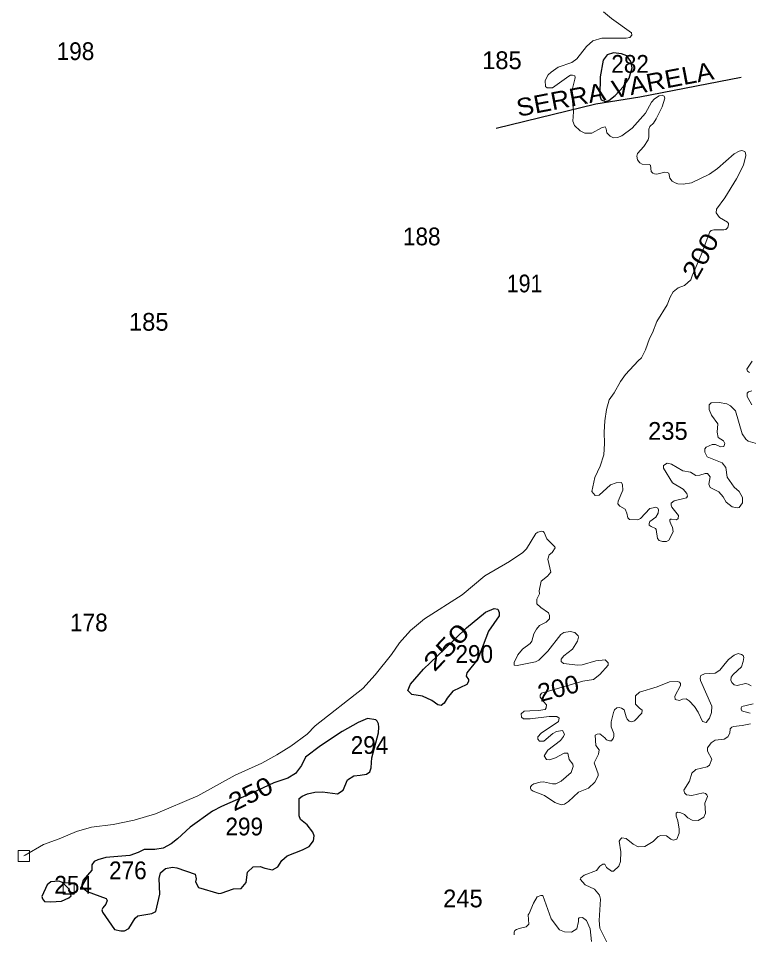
# Model space of a CAD drawing. Extents: x 499.9 to 555.3, y 9281.5 to 9336.8.
# Drawn here: x 499.95 to 506.54, y 9288.5 to 9296.75 of the extents above; entities that cross this region are included whole.
import ezdxf
from ezdxf.enums import TextEntityAlignment as Align

# ---------------------------------------------------------------- set-up
doc = ezdxf.new("R2010")
doc.units = 0
doc.header["$LTSCALE"] = 0.064
for name, color, linetype, lineweight in [('1', 7, 'Continuous', 25), ('2', 7, 'Continuous', 13), ('26', 7, 'Continuous', 25), ('62', 7, 'Continuous', 13)]:
    doc.layers.add(name, color=color, linetype=linetype, lineweight=lineweight)
doc.layers.add('21', color=7, linetype='Continuous')
doc.layers.add('61', color=7, linetype='Continuous')

msp = doc.modelspace()

# ---------------------------------------------------------------- linework, layer by layer
at = {"layer": '1'}
for points in [[(505.3309, 9296.058), (505.407, 9296.1414), (505.4595, 9296.2165), (505.485, 9296.3096), (505.4745, 9296.3666), (505.4378, 9296.4165), (505.3896, 9296.436), (505.3169, 9296.4447), (505.2599, 9296.4266), (505.2231, 9296.3782), (505.1979, 9296.2277), (505.1944, 9296.0552), (505.207, 9296.0211), (505.2446, 9296.0061), (505.2762, 9296.0136)], [(503.6048, 9290.8873), (503.793, 9291.0695), (503.9922, 9291.2624), (504.1617, 9291.4023), (504.2416, 9291.4356), (504.2728, 9291.4305), (504.2868, 9291.3979), (504.2847, 9291.3702), (504.1912, 9291.23), (504.0936, 9290.978), (503.9949, 9290.8566), (503.9871, 9290.8241), (504.0098, 9290.795), (504.011, 9290.7771), (503.9932, 9290.7503), (503.867, 9290.6911), (503.8173, 9290.6278), (503.7889, 9290.5817), (503.762, 9290.5613), (503.7325, 9290.5664), (503.6782, 9290.6057), (503.5938, 9290.6463), (503.4983, 9290.661), (503.4615, 9290.6964), (503.4856, 9290.7541)], [(503.1208, 9289.9623), (503.1331, 9289.9996), (503.1346, 9290.048), (503.1381, 9290.088), (503.1989, 9290.3153), (503.2024, 9290.3649), (503.1968, 9290.3964), (503.185, 9290.4208), (503.1741, 9290.4331), (503.0991, 9290.4427), (503.0157, 9290.4061), (502.8707, 9290.3254), (502.6737, 9290.1977), (502.5397, 9290.0959), (502.5023, 9290.0206), (502.4493, 9289.9487), (502.3795, 9289.9064), (502.2536, 9289.8648), (502.0553, 9289.771), (501.7833, 9289.6508), (501.6999, 9289.6078), (501.4986, 9289.4656), (501.3849, 9289.3602), (501.3274, 9289.3152), (501.2577, 9289.2756), (501.1802, 9289.2622), (501.0838, 9289.262), (501.0306, 9289.2351), (500.9566, 9289.2095), (500.7379, 9289.1919), (500.6668, 9289.1704), (500.6354, 9289.1537), (500.6142, 9289.1242), (500.613, 9289.0769), (500.5357, 9288.9851), (500.5227, 9288.9438), (500.5298, 9288.9191), (500.5699, 9288.885), (500.7434, 9288.8224), (500.7505, 9288.804), (500.7379, 9288.7704), (500.7113, 9288.7382), (500.7043, 9288.72), (500.7098, 9288.6965), (500.8164, 9288.5409), (500.8736, 9288.5283), (500.9063, 9288.529), (500.9478, 9288.5508), (501.0037, 9288.6445), (501.0271, 9288.6647), (501.154, 9288.6859), (501.1895, 9288.7037), (501.2247, 9288.8611), (501.219, 9289.0022), (501.2323, 9289.054), (501.2768, 9289.0906), (501.3418, 9289.104), (501.3797, 9289.0974), (501.5454, 9289.0394), (501.5525, 9288.998), (501.5485, 9288.9701), (501.5756, 9288.9217), (501.7589, 9288.8673), (501.7787, 9288.8681), (501.8893, 9288.9084), (501.9592, 9288.9121), (502.0043, 9288.9662), (502.0178, 9289.0597), (502.0678, 9289.1054), (502.132, 9289.1092), (502.1735, 9289.0934), (502.242, 9289.08), (502.2909, 9289.1064), (502.3253, 9289.1639), (502.3741, 9289.2062), (502.5116, 9289.2593), (502.5725, 9289.2898), (502.6129, 9289.34), (502.6173, 9289.387), (502.6057, 9289.4203), (502.5536, 9289.4849), (502.4956, 9289.5338), (502.4812, 9289.5676), (502.4836, 9289.7214), (502.5109, 9289.7426), (502.5568, 9289.7642), (502.6246, 9289.7807), (502.6922, 9289.7825), (502.8298, 9289.7657), (502.8782, 9289.7971), (502.9188, 9289.8915), (502.9764, 9289.9273), (503.0337, 9289.9325), (503.0889, 9289.9422)]]:
    msp.add_lwpolyline(points, close=True, dxfattribs=at)
msp.add_lwpolyline([(500.4036, 9288.9116), (500.3499, 9288.9664), (500.3139, 9288.9788), (500.2434, 9288.9701), (500.2098, 9288.943), (500.1632, 9288.8379), (500.1678, 9288.8193), (500.186, 9288.7956), (500.2441, 9288.7898), (500.3379, 9288.7985), (500.4041, 9288.827), (500.4255, 9288.8447), (500.405, 9288.9131)], dxfattribs=at)
at = {"layer": '2'}
for points in [[(505.2266, 9296.8135), (505.2993, 9296.752), (505.4793, 9296.6254), (505.4831, 9296.602), (505.4639, 9296.5832), (505.4305, 9296.5771), (505.2133, 9296.5752), (505.1306, 9296.5513), (505.0747, 9296.5005), (504.9872, 9296.3896), (504.9411, 9296.3575), (504.8186, 9296.3159), (504.7543, 9296.2708), (504.7286, 9296.2448), (504.7017, 9296.1951), (504.7046, 9296.1405), (504.7194, 9296.1287), (504.7682, 9296.1271), (504.9135, 9296.2342), (504.9309, 9296.2422), (504.948, 9296.244), (504.9676, 9296.2375), (504.9715, 9296.2219), (504.9696, 9296.2063), (504.9464, 9296.1219), (504.9412, 9296.0787), (504.9553, 9295.9132), (504.9491, 9295.8292), (504.9663, 9295.7883), (505.017, 9295.7403), (505.0592, 9295.7191), (505.1209, 9295.7208), (505.2094, 9295.768), (505.2417, 9295.7757), (505.2517, 9295.7603), (505.2585, 9295.7218), (505.2881, 9295.6921), (505.3175, 9295.6779), (505.3533, 9295.6795), (505.3931, 9295.6953), (505.4854, 9295.7637), (505.6062, 9295.9005), (505.659, 9296), (505.6875, 9296.0299), (505.7296, 9296.0567), (505.7552, 9296.0633), (505.774, 9296.0539), (505.781, 9296.0363), (505.7574, 9295.9577), (505.7024, 9295.8482), (505.6766, 9295.8102), (505.6448, 9295.7799), (505.6366, 9295.7573), (505.6354, 9295.6861), (505.63, 9295.6602), (505.5919, 9295.5982), (505.5348, 9295.5368), (505.5286, 9295.5112), (505.5329, 9295.4788), (505.5534, 9295.4523), (505.5748, 9295.4413), (505.6395, 9295.4385), (505.6509, 9295.4314), (505.6561, 9295.3757), (505.6722, 9295.3597), (505.6869, 9295.3546), (505.7075, 9295.3511), (505.7809, 9295.3676), (505.801, 9295.3666), (505.8162, 9295.3593), (505.825, 9295.3136), (505.8461, 9295.2872), (505.8735, 9295.2709), (505.8985, 9295.2639), (505.9445, 9295.2595), (506.0218, 9295.2719)], [(506.4746, 9295.5625), (506.5012, 9295.5531), (506.5088, 9295.5393), (506.51, 9295.5199), (506.4894, 9295.4319), (506.4264, 9295.3091), (506.3214, 9295.1372), (506.2446, 9295.0355), (506.2426, 9295.0016), (506.2737, 9294.9595), (506.3441, 9294.9171), (506.3542, 9294.906), (506.3552, 9294.8963), (506.3476, 9294.8695), (506.3306, 9294.8527), (506.3126, 9294.8477), (506.2219, 9294.8487), (506.1978, 9294.8422), (506.1853, 9294.8311), (506.108, 9294.623), (506.0273, 9294.4333), (506.0141, 9294.3964), (505.9569, 9294.3477), (505.9009, 9294.3247), (505.8552, 9294.2881), (505.8277, 9294.2421), (505.801, 9294.1735), (505.7067, 9294.0224), (505.6703, 9293.9214), (505.6407, 9293.8679), (505.606, 9293.7671), (505.57, 9293.6937), (505.5387, 9293.6682), (505.426, 9293.5442), (505.3789, 9293.4813), (505.3247, 9293.3796), (505.2769, 9293.3166), (505.2548, 9293.2275), (505.2388, 9293.1256), (505.2324, 9293.0237), (505.2371, 9292.9211), (505.229, 9292.8192), (505.1976, 9292.7182), (505.1481, 9292.6155), (505.1212, 9292.489), (505.1514, 9292.4551), (505.1893, 9292.4582), (505.2897, 9292.5486), (505.3406, 9292.5692), (505.3879, 9292.5704), (505.398, 9292.5487), (505.4006, 9292.5018), (505.3586, 9292.4029), (505.3577, 9292.3772), (505.3734, 9292.3578), (505.4225, 9292.3307), (505.4386, 9292.2946), (505.447, 9292.2533), (505.4625, 9292.237), (505.5354, 9292.234), (505.5601, 9292.2465), (505.6456, 9292.3379), (505.6748, 9292.3431), (505.6998, 9292.3475), (505.716, 9292.3391), (505.7231, 9292.3242), (505.7189, 9292.2941), (505.6986, 9292.2584), (505.6457, 9292.2197), (505.6398, 9292.2002), (505.6396, 9292.1862), (505.6574, 9292.1732), (505.696, 9292.1565), (505.7034, 9292.1462), (505.7153, 9292.0675), (505.7291, 9292.0496), (505.7587, 9292.0387), (505.7963, 9292.0383), (505.8157, 9292.0518), (505.8558, 9292.1254), (505.8501, 9292.1681), (505.8373, 9292.1906), (505.8254, 9292.2209), (505.8254, 9292.2341), (505.8301, 9292.2416), (505.8404, 9292.2416), (505.8856, 9292.2352), (505.9011, 9292.2459), (505.9031, 9292.2743), (505.8434, 9292.3472), (505.8374, 9292.3672), (505.8387, 9292.3847), (505.8637, 9292.4042), (505.9744, 9292.4333), (505.9833, 9292.4475)], [(506.0218, 9295.2719), (506.1818, 9295.3511), (506.2539, 9295.4003), (506.4054, 9295.5327), (506.4501, 9295.5581), (506.4746, 9295.5625)], [(506.5439, 9293.5627), (506.5242, 9293.5735), (506.5193, 9293.5925), (506.5686, 9293.6653)], [(506.564, 9293.2719), (506.5215, 9293.345), (506.5234, 9293.3761), (506.536, 9293.3873), (506.5638, 9293.3969)], [(505.7676, 9292.7236), (505.8013, 9292.7457), (505.8403, 9292.7363), (505.9416, 9292.6766), (506.0122, 9292.6646), (506.0593, 9292.6349), (506.0958, 9292.6381), (506.1451, 9292.6534), (506.1649, 9292.6517), (506.19, 9292.6214), (506.178, 9292.5558), (506.1877, 9292.5266), (506.2674, 9292.4859), (506.3076, 9292.4426), (506.333, 9292.3942), (506.3863, 9292.351), (506.4324, 9292.3419), (506.4514, 9292.3453), (506.4798, 9292.3865), (506.4798, 9292.4371), (506.4495, 9292.4887), (506.4054, 9292.5296), (506.3411, 9292.6204), (506.3299, 9292.7052), (506.2962, 9292.7478), (506.1632, 9292.8027), (506.1398, 9292.8448), (506.1397, 9292.8741), (506.152, 9292.8902), (506.2077, 9292.9139), (506.2357, 9292.9143), (506.2833, 9292.8911), (506.3127, 9292.8965), (506.3222, 9292.9227), (506.3103, 9292.9466), (506.2605, 9292.9777), (506.2511, 9293.0261), (506.2568, 9293.1), (506.2022, 9293.1783), (506.1796, 9293.2299), (506.1811, 9293.2702), (506.1993, 9293.2891), (506.2692, 9293.2935), (506.3407, 9293.2803), (506.3719, 9293.2616), (506.418, 9293.2164), (506.4768, 9293.011), (506.512, 9292.961), (506.5303, 9292.9448), (506.6589, 9292.9061)], [(505.9833, 9292.4475), (505.9797, 9292.4728), (505.9442, 9292.5118), (505.8505, 9292.568), (505.7677, 9292.7009), (505.7676, 9292.7236)], [(504.5671, 9291.1183), (504.5798, 9291.141), (504.599, 9291.2054), (504.6226, 9291.2484), (504.6495, 9291.2812), (504.7103, 9291.3106), (504.7386, 9291.3424), (504.7394, 9291.3712), (504.7319, 9291.3967), (504.6612, 9291.4437), (504.6271, 9291.4773), (504.6247, 9291.5204), (504.6496, 9291.5667), (504.6471, 9291.5938), (504.666, 9291.6812), (504.7235, 9291.7281), (504.7529, 9291.7614), (504.7249, 9291.8793), (504.7376, 9291.9183), (504.7632, 9291.9414), (504.7899, 9291.9833), (504.7893, 9291.9922), (504.7165, 9292.0624), (504.6928, 9292.1198), (504.6826, 9292.1279), (504.6669, 9292.1311), (504.6348, 9292.1237), (504.6182, 9292.1125), (504.5324, 9291.9733), (504.4986, 9291.9407), (504.3803, 9291.8591), (504.1558, 9291.7286), (503.9529, 9291.5586), (503.6138, 9291.3407), (503.4859, 9291.2367), (503.3874, 9291.1258), (503.3166, 9291.0215), (503.1678, 9290.8377), (503.0568, 9290.7135), (502.6281, 9290.3785), (502.5543, 9290.3018), (502.4067, 9290.1943), (502.2809, 9290.1147), (502.1447, 9290.0419), (501.9068, 9289.9325), (501.5679, 9289.7456), (501.1874, 9289.5854), (500.9942, 9289.5284), (500.8049, 9289.4888), (500.6113, 9289.4644), (500.4743, 9289.4264), (500.3169, 9289.359), (500.1762, 9289.309), (500.0105, 9289.2112), (500, 9289.205)], [(505.2397, 9290.2701), (505.1948, 9290.3041), (505.1695, 9290.3014), (505.1525, 9290.2921), (505.1585, 9290.1991), (505.1872, 9290.1618), (505.1812, 9290.1208), (505.1437, 9290.0443), (505.1797, 9289.9443), (505.178, 9289.9276), (505.1493, 9289.8701), (505.0922, 9289.8144), (505.0028, 9289.7785), (504.9128, 9289.6957), (504.8742, 9289.6713), (504.844, 9289.6664), (504.7878, 9289.686), (504.6944, 9289.7507), (504.5933, 9289.7872), (504.5736, 9289.801), (504.5675, 9289.8155), (504.5698, 9289.8288), (504.5811, 9289.8425), (504.5994, 9289.8535), (504.6547, 9289.8712), (504.6858, 9289.8729), (504.7676, 9289.8543), (504.797, 9289.8562), (504.8454, 9289.8788), (504.9349, 9289.9563), (504.9535, 9290.0109), (504.9516, 9290.0329), (504.9175, 9290.0755), (504.9067, 9290.1309), (504.8711, 9290.132), (504.7931, 9290.0898), (504.7414, 9290.0724), (504.7141, 9290.0749), (504.6934, 9290.1061), (504.7238, 9290.1569), (504.8378, 9290.2445), (504.8658, 9290.28), (504.8753, 9290.302), (504.8585, 9290.334), (504.8039, 9290.3272), (504.7687, 9290.3072), (504.6879, 9290.2396), (504.6493, 9290.2386), (504.6341, 9290.2575), (504.6346, 9290.2796), (504.6653, 9290.3105), (504.8221, 9290.4167), (504.8268, 9290.4471), (504.8058, 9290.4621), (504.7358, 9290.4605), (504.5647, 9290.4399), (504.5049, 9290.4399), (504.487, 9290.4548), (504.4848, 9290.486), (504.5119, 9290.5086), (504.5624, 9290.5142), (504.6403, 9290.5147), (504.7006, 9290.5261), (504.7113, 9290.5394), (504.712, 9290.5672), (504.6864, 9290.5973), (504.6549, 9290.637), (504.6553, 9290.6549), (504.6686, 9290.6722), (504.8549, 9290.7264), (505.0412, 9290.7806), (505.1373, 9290.7959), (505.1946, 9290.8393), (505.2686, 9290.9238), (505.2703, 9290.946), (505.2417, 9290.9729), (505.1592, 9290.9635), (505.0343, 9290.9284), (504.9944, 9290.9253), (504.8673, 9290.9384), (504.8445, 9290.9588), (504.8446, 9290.9782), (504.8707, 9291.0091), (504.9478, 9291.0676), (504.9934, 9291.1403), (505.0027, 9291.1782), (504.9993, 9291.1901), (504.968, 9291.2195), (504.9261, 9291.229), (504.8685, 9291.2182), (504.8435, 9291.2), (504.7262, 9291.0494), (504.6435, 9290.9684), (504.6131, 9290.9551), (504.4494, 9290.9207)], [(504.4494, 9290.9207), (504.4225, 9290.9246), (504.4226, 9290.9498), (504.4538, 9291.0169), (504.4972, 9291.0701), (504.5671, 9291.1183)], [(506.5587, 9290.7368), (506.5324, 9290.754), (506.5087, 9290.7581), (506.4313, 9290.742), (506.4047, 9290.7473), (506.3829, 9290.7691), (506.3763, 9290.79), (506.3769, 9290.8162), (506.3965, 9290.8415), (506.4701, 9290.9089), (506.488, 9290.9571), (506.492, 9290.9948), (506.4866, 9291.0117), (506.4725, 9291.0217), (506.4426, 9291.0281), (506.4063, 9291.0139), (506.3552, 9290.9767), (506.3129, 9290.9251), (506.2774, 9290.8789), (506.2332, 9290.853), (506.1365, 9290.8456), (506.1042, 9290.8313), (506.0984, 9290.8067), (506.1015, 9290.7852), (506.2031, 9290.5552), (506.2019, 9290.4982), (506.184, 9290.4479), (506.1536, 9290.4086), (506.1188, 9290.4169), (506.0802, 9290.4994), (506.0476, 9290.5521), (505.9981, 9290.6031), (505.9716, 9290.6211), (505.9398, 9290.6181), (505.9135, 9290.6057), (505.8723, 9290.6143), (505.8699, 9290.6436), (505.9213, 9290.7406), (505.9228, 9290.7596), (505.9128, 9290.7725), (505.8944, 9290.7771), (505.8216, 9290.7734), (505.7123, 9290.7277), (505.5516, 9290.6819), (505.5164, 9290.6472), (505.5148, 9290.5715), (505.5502, 9290.536), (505.5758, 9290.5201), (505.5729, 9290.4915), (505.5052, 9290.4228), (505.4838, 9290.4132), (505.4578, 9290.42), (505.4413, 9290.4387), (505.4304, 9290.4592), (505.4135, 9290.5223), (505.3904, 9290.5379), (505.3695, 9290.5425), (505.3472, 9290.5408), (505.3277, 9290.5218), (505.3166, 9290.4991), (505.2963, 9290.4136), (505.2949, 9290.3685), (505.3208, 9290.3082), (505.3211, 9290.2804)], [(506.551, 9290.4925), (506.4923, 9290.5065), (506.4755, 9290.514), (506.4678, 9290.5273), (506.4684, 9290.5389), (506.4746, 9290.5506), (506.5125, 9290.5603), (506.577, 9290.576)], [(506.2029, 9290.0762), (506.1659, 9290.15), (506.1651, 9290.1788), (506.1991, 9290.2254), (506.2351, 9290.2486), (506.3146, 9290.2587), (506.348, 9290.2783), (506.3669, 9290.3109), (506.3705, 9290.3498), (506.3847, 9290.3665), (506.3998, 9290.3724), (506.4787, 9290.3796), (506.5541, 9290.3956)], [(505.3211, 9290.2804), (505.3148, 9290.2635), (505.2985, 9290.2414), (505.2804, 9290.2417), (505.2542, 9290.2516), (505.2397, 9290.2701)], [(506.0026, 9289.878), (506.0227, 9289.9506), (506.0601, 9289.9844), (506.1628, 9290.0085), (506.1828, 9290.0236), (506.2029, 9290.0762)], [(505.2581, 9288.4268), (505.1942, 9288.554), (505.1894, 9288.6225), (505.2004, 9288.8141), (505.191, 9288.8522), (505.1463, 9288.9039), (505.0627, 9288.9431), (505.018, 9288.9948), (505.0225, 9289.0088), (505.0524, 9289.0319), (505.1632, 9289.0725), (505.1944, 9289.1139), (505.2223, 9289.1296), (505.2385, 9289.1294), (505.2544, 9289.1007), (505.2977, 9289.0667), (505.3182, 9289.0667), (505.3643, 9289.1126), (505.3817, 9289.1558), (505.3835, 9289.2414), (505.3693, 9289.3369), (505.3795, 9289.3564), (505.3927, 9289.3665), (505.4323, 9289.3609), (505.4933, 9289.3122), (505.5383, 9289.2867), (505.5991, 9289.2911), (505.6747, 9289.3339), (505.7204, 9289.3792), (505.7442, 9289.3891), (505.7951, 9289.3847), (505.8334, 9289.3548), (505.8591, 9289.3473), (505.8883, 9289.3567), (505.9103, 9289.4087), (505.9102, 9289.4459), (505.8977, 9289.5208), (505.8828, 9289.5623), (505.8826, 9289.5897), (505.8933, 9289.5995), (505.9247, 9289.5939), (505.9573, 9289.5775), (505.9884, 9289.547), (506.0267, 9289.5262), (506.0822, 9289.5233), (506.1324, 9289.5529), (506.1458, 9289.5916), (506.1397, 9289.6799), (506.1642, 9289.7399), (506.1597, 9289.7562), (506.1468, 9289.7671), (506.1245, 9289.7726), (506.0232, 9289.7493), (505.9747, 9289.7554), (505.9573, 9289.7741), (505.9522, 9289.7991), (506.0026, 9289.878)], [(504.4223, 9288.4939), (504.4216, 9288.5162), (504.428, 9288.5318), (504.4432, 9288.5429), (504.4677, 9288.5502), (504.5302, 9288.5659), (504.5528, 9288.591), (504.5483, 9288.6753), (504.5575, 9288.6853), (504.5949, 9288.7782), (504.63, 9288.8359), (504.6626, 9288.8496), (504.6792, 9288.8469), (504.755, 9288.6364), (504.83, 9288.5389), (504.8744, 9288.5218), (504.939, 9288.5177), (504.9873, 9288.5468), (505.0014, 9288.6143), (505.0002, 9288.6405), (505.008, 9288.6481), (505.038, 9288.6489), (505.0726, 9288.6223), (505.1065, 9288.5475), (505.1197, 9288.4322)]]:
    msp.add_lwpolyline(points, dxfattribs=at)
at = {"layer": '26'}
msp.add_lwpolyline([(504.2589, 9295.7662), (505.1579, 9295.984), (505.5539, 9296.0474), (506.4688, 9296.2256)], dxfattribs=at)
at = {"layer": '62'}
for points in [[(499.95, 9289.255), (500.05, 9289.255), (500.05, 9289.155), (499.95, 9289.155)], [(500.3536, 9288.9616), (500.4536, 9288.9616), (500.4536, 9288.8616), (500.3536, 9288.8616)], [(500.355, 9288.9631), (500.455, 9288.9631), (500.455, 9288.8631), (500.355, 9288.8631)]]:
    msp.add_lwpolyline(points, close=True, dxfattribs=at)

# ---------------------------------------------------------------- texts
at = {"layer": '21'}
for s, width, p in [('198', 0.95, (500.2961, 9296.3787)), ('282', 0.95, (505.2972, 9296.2642)), ('188', 0.95, (503.4185, 9294.7089)), ('191', 0.9, (504.3549, 9294.2849)), ('178', 0.95, (500.4166, 9291.2293)), ('290', 0.95, (503.8919, 9290.9454)), ('294', 0.95, (502.9475, 9290.1244)), ('299', 0.95, (501.8178, 9289.3898)), ('276', 0.95, (500.7684, 9288.9947)), ('254', 0.95, (500.2746, 9288.8651))]:
    msp.add_text(s, height=0.16, dxfattribs=dict(at, width=width)).set_placement(p)
for s, p in [('185', (504.1327, 9296.2973)), ('185', (500.9475, 9293.9392)), ('235', (505.6294, 9292.9557)), ('245', (503.7808, 9288.7416))]:
    msp.add_text(s, height=0.16, dxfattribs=at).set_placement(p)
at = {"layer": '26', "width": 1.1}
msp.add_text('SERRA VARELA', height=0.16, rotation=10.87, dxfattribs=at).set_placement((505.3449, 9296.0369), align=Align.CENTER)
at = {"layer": '61'}
for s, rotation, width, p in [('200', 60.488, 1.2, (506.1713, 9294.5723)), ('250', 46.782, 1.35, (503.8677, 9291.0322)), ('200', 14.673, 1.05, (504.8391, 9290.6396)), ('250', 26.03, 1.15, (502.0794, 9289.6938))]:
    msp.add_text(s, height=0.16, rotation=rotation, dxfattribs=dict(at, width=width)).set_placement(p, align=Align.CENTER)

doc.saveas('drawing.dxf')
